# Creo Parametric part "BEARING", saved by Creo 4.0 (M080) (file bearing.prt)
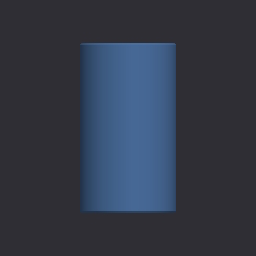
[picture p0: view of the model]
Units: Inch lbm Second (Pro/E Default); INCH, POUND, SECS

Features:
  1. datum plane "DTM1"
  2. datum plane "DTM2"
  3. datum plane "DTM3"
  4. protrusion
  5. cut
  6. chamfer

Layers: 1, 2, 3, 4, 5, 6, 7, 8, 9, 10, 11, 12, 13, 14, 15, 16, 17, 18, 19, 20, 21, 22, 23, 24, 25, 26, 27, 28, 29, 30, 31, 32, BLANK

Surfaces: 8 cone, 5 cylinder, 2 plane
